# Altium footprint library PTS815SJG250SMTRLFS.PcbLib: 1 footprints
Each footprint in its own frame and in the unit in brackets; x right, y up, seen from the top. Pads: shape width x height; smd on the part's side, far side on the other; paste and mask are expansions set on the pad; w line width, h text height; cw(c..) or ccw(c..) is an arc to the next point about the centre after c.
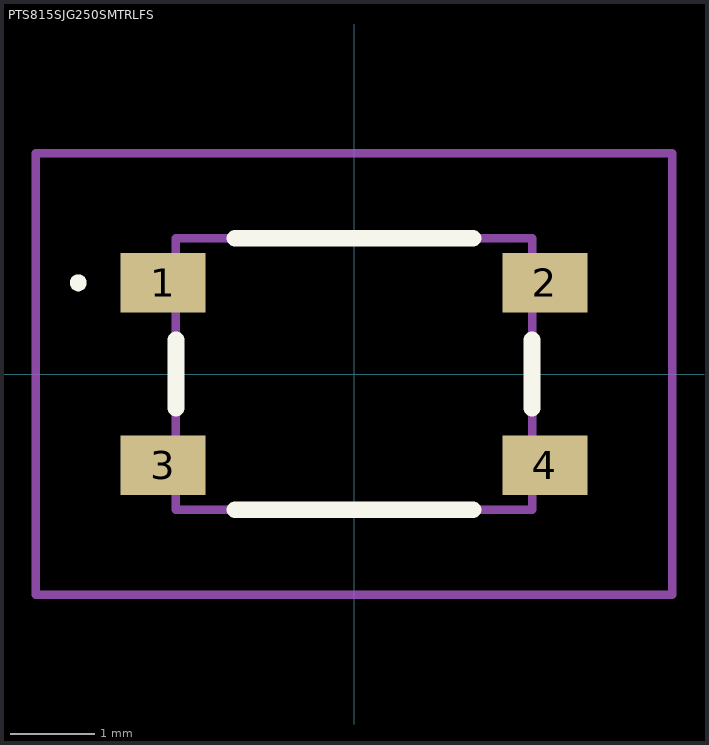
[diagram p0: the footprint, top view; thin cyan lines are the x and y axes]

## PTS815SJG250SMTRLFS [mm]
pads (4):
  rect 1x0.7 smd: 1(-2.25,1.075) 2(2.25,1.075) 3(-2.25,-1.075) 4(2.25,-1.075)
Top Overlay:
  lines w0.1: -3.3,1.075 -3.3,1.075 ; -3.3,1.075 ccw(c-3.25,1.075) -3.2,1.075 ; -3.3,1.075 cw(c-3.25,1.075) -3.2,1.075 ; -3.2,1.075 -3.2,1.075
  lines w0.2: -2.1,-0.4 -2.1,0.4 ; -1.4,-1.6 1.4,-1.6 ; -1.4,1.6 1.4,1.6 ; 2.1,-0.4 2.1,0.4
Mechanical 15:
  lines w0.1: -2.1,-1.6 2.1,-1.6 2.1,1.6 -2.1,1.6 -2.1,-1.6
Mechanical 20:
  lines w0.1: -3.75,-2.6 3.75,-2.6 3.75,2.6 -3.75,2.6 -3.75,-2.6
